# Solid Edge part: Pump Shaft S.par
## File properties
Title: Pump Shaft
Author: Dan
Template: Pump Shaft.par
Last saved by: Dan
Revision: 10
Application: Solid Edge
Material: aluminum
Density: 7.85 kg/dm^3
Accuracy: 0.99
Document Number: P52-003
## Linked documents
Pump Shaft.par
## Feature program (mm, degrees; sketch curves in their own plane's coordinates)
part copy "CopiedPart_1"
sketch for "unnamed RevolvedProtrusion 1" #1 plane through (0, 0, 0) normal (1, 0, 0) x-axis (0, 1, 0)
sketch for "unnamed RevolvedProtrusion 1" #2 plane through (0, 0, 0) normal (1, 0, 0) x-axis (0, 1, 0)
revolve "unnamed RevolvedProtrusion 1" add finite 360 deg about sketch line (0, 106) -> (0, 43)
sketch for "unnamed RevolvedProtrusion 2" plane through (0, 0, 0) normal (1, 0, 0) x-axis (0, 1, 0)
revolve "unnamed RevolvedProtrusion 2" add finite 360 deg about sketch line (-1.147, 147.5495) -> (6.8932, 121.2511)
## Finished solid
Body 1: solid body, 146 faces, 376 edges, 234 vertices.
  Faces by surface: cylinder 69, plane 51, cone 21, torus 4, spline 1
  Edges by curve: circle 147, line 138, intersection 79, ellipse 10, curve on surface 2
Bounding box of the edges (mm; curved faces can reach further): 90.000 x 84.576 x 189.500, from (-45, -39.5763, 0) to (45.0001, 45, 189.5).
Cylindrical faces by radius (mm): R0.6 x1, R0.8 x20, R2 x1, R4 x1, R5 x1, R14.4 x1, R15 x1, R15.9 x10, R16.4 x1, R16.7 x8, R17.4 x16, R17.9 x2, R20 x1, R21.25 x1, R22.4 x3, R45 x1
Conical faces (half-angle, radius in mm at the cone's reference point): 17 deg R34.7934 x1, 30 deg R4 x1, 45 deg R14.4 x1, 45 deg R19.1444 x16, 59 deg R2 x1, 73 deg R43.3682 x1
Toroidal faces (ring radius, tube radius in mm): R17 r3 x1, R42.491 r3 x1, R44.4 r0.6 x2
Planar faces by outward normal: +x 3, +y 2, +z 11, -x 3, -y 2, -z 16, oblique 14
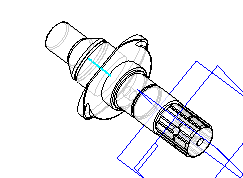
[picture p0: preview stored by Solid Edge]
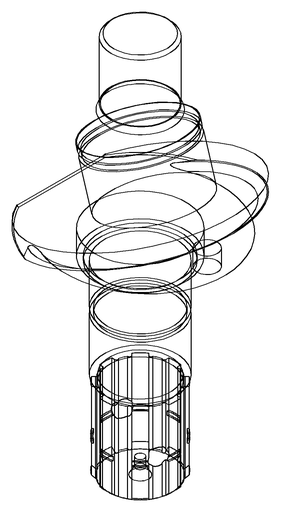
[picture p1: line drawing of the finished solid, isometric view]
